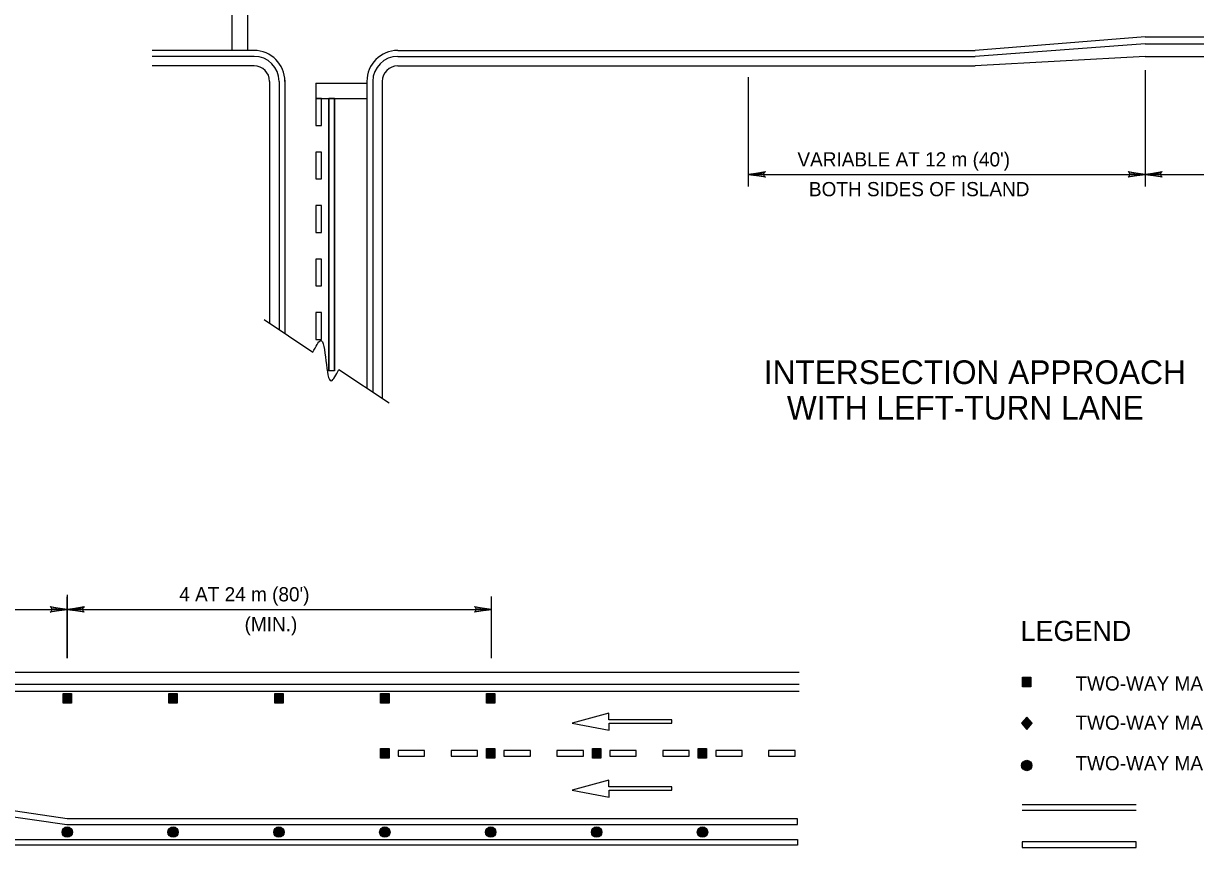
# Model space of a CAD drawing. Extents: x 639362 to 641108, y 298458 to 299646.
# Drawn here: x 639788.7 to 640036.4, y 298754.6 to 298928.7 of the extents above; entities that cross this region are included whole.
import ezdxf

# ---------------------------------------------------------------- set-up
doc = ezdxf.new("R2010")
doc.units = 0
doc.layers.add('2', color=7, linetype='Continuous')
doc.layers.add('3', color=7, linetype='Continuous')

# ---------------------------------------------------------------- blocks, each defined once
blk = doc.blocks.new('RARROW')
at = {"layer": '3'}
blk.add_lwpolyline([(-2.2695, 0.285), (-2.184875, 0.12075), (0, 0), (-2.2695, 0.285), (-2.38575, 0.384625), (0, 0), (-2.183125, -0.108), (-2.262875, -0.2705), (0, 0), (-2.38575, -0.379125), (-2.262875, -0.2705)], dxfattribs=at)

msp = doc.modelspace()

# ---------------------------------------------------------------- linework, layer by layer
at = {"layer": '2'}
for p, q in [((639832.85, 298922.95), (639832.85, 298950.59)), ((639836.15, 298922.95), (639836.15, 298950.59)), ((640025.73, 298925.85), (639989.83, 298922.95)), ((640025.73, 298925.85), (640169.33, 298925.85)), ((639837.77, 298922.95), (639815.93, 298922.95)), ((639867.83, 298922.95), (639989.83, 298922.95)), ((640025.73, 298924.35), (639989.83, 298921.72)), ((640025.73, 298924.35), (640169.33, 298924.35)), ((639837.47, 298921.72), (639815.93, 298921.72)), ((639837.47, 298919.72), (639815.93, 298919.72)), ((639867.83, 298921.72), (639989.83, 298921.72)), ((639867.83, 298919.72), (639989.83, 298919.72)), ((640025.73, 298921.72), (639989.83, 298919.72)), ((640025.73, 298921.72), (640169.33, 298921.72)), ((639941.89, 298917.32), (639941.89, 298894.23)), ((640025.73, 298918.79), (640025.73, 298894.23)), ((639840.75, 298916.44), (639840.75, 298865.35)), ((639842.75, 298916.44), (639842.75, 298864.01)), ((639843.98, 298916.69), (639843.98, 298863.19)), ((639850.53, 298916.09), (639850.53, 298912.79)), ((639850.53, 298916.09), (639861.32, 298916.09)), ((639861.32, 298916.53), (639861.32, 298851.64)), ((639862.55, 298916.44), (639862.55, 298850.81)), ((639864.55, 298916.44), (639864.55, 298849.48)), ((639850.53, 298912.79), (639861.32, 298912.79)), ((639854.47, 298912.79), (639853.27, 298912.79)), ((639853.27, 298912.79), (639853.27, 298855.27)), ((639853.27, 298855.27), (639853.27, 298912.79)), ((639853.27, 298912.79), (639854.47, 298912.79)), ((639854.47, 298855.27), (639854.47, 298912.79)), ((639854.47, 298912.79), (639854.47, 298855.27)), ((639941.89, 298896.78), (640025.73, 298896.78)), ((640025.73, 298896.78), (640169.33, 298896.78)), ((639839.62, 298866.1), (639849.91, 298859.24)), ((639854.47, 298855.27), (639853.27, 298855.27)), ((639855.4, 298855.58), (639866.03, 298848.49)), ((639797.99, 298807.92), (639797.99, 298794.58)), ((639798, 298794.58), (639798, 298807.5)), ((639887.61, 298794.58), (639887.61, 298807.59)), ((639585.52, 298804.88), (639797.99, 298804.88)), ((639798.01, 298804.88), (639887.61, 298804.88)), ((639431.25, 298791.58), (639952.64, 298791.58)), ((639789.19, 298791.58), (639951.12, 298791.58)), ((639431.25, 298789.08), (639952.64, 298789.08)), ((639789.84, 298789.08), (639951.12, 298789.08)), ((639999.84, 298790.57), (640001.61, 298790.57)), ((639999.84, 298788.53), (639999.84, 298790.57)), ((640001.61, 298788.53), (639999.84, 298788.53)), ((640000.01, 298790.4), (640001.43, 298790.4)), ((640000.01, 298788.71), (640000.01, 298790.4)), ((640001.43, 298788.71), (640000.01, 298788.71)), ((640000.19, 298790.22), (640001.26, 298790.22)), ((640000.19, 298788.89), (640000.19, 298790.22)), ((640001.26, 298788.89), (640000.19, 298788.89)), ((640000.37, 298789.07), (640000.37, 298790.04)), ((640000.37, 298790.04), (640001.08, 298790.04)), ((640001.08, 298789.07), (640000.37, 298789.07)), ((640000.55, 298789.87), (640000.9, 298789.87)), ((640000.55, 298789.24), (640000.55, 298789.87)), ((640000.9, 298789.24), (640000.55, 298789.24)), ((640000.72, 298789.69), (640000.72, 298789.42)), ((640000.9, 298789.87), (640000.9, 298789.24)), ((640001.08, 298790.04), (640001.08, 298789.07)), ((640001.26, 298790.22), (640001.26, 298788.89)), ((640001.43, 298790.4), (640001.43, 298788.71)), ((640001.61, 298790.57), (640001.61, 298788.53)), ((639431.25, 298787.58), (639952.64, 298787.58)), ((639790.24, 298787.58), (639951.12, 298787.58)), ((639797.11, 298785.06), (639797.11, 298787.1)), ((639797.11, 298787.1), (639798.88, 298787.1)), ((639797.28, 298785.23), (639797.28, 298786.92)), ((639797.28, 298786.92), (639798.7, 298786.92)), ((639797.46, 298785.41), (639797.46, 298786.74)), ((639797.46, 298786.74), (639798.53, 298786.74)), ((639797.64, 298785.59), (639797.64, 298786.56)), ((639797.64, 298786.56), (639798.35, 298786.56)), ((639797.82, 298785.76), (639797.82, 298786.39)), ((639797.82, 298786.39), (639798.17, 298786.39)), ((639798.17, 298785.76), (639797.82, 298785.76)), ((639798, 298785.94), (639798, 298786.21)), ((639798.17, 298786.39), (639798.17, 298785.76)), ((639798.35, 298786.56), (639798.35, 298785.59)), ((639798.53, 298786.74), (639798.53, 298785.41)), ((639798.7, 298786.92), (639798.7, 298785.23)), ((639798.88, 298787.1), (639798.88, 298785.06)), ((639819.47, 298785.06), (639819.47, 298787.1)), ((639819.47, 298787.1), (639821.25, 298787.1)), ((639819.65, 298785.23), (639819.65, 298786.92)), ((639819.65, 298786.92), (639821.07, 298786.92)), ((639819.83, 298785.41), (639819.83, 298786.74)), ((639819.83, 298786.74), (639820.89, 298786.74)), ((639820.01, 298785.59), (639820.01, 298786.56)), ((639820.01, 298786.56), (639820.72, 298786.56)), ((639820.18, 298785.76), (639820.18, 298786.39)), ((639820.18, 298786.39), (639820.54, 298786.39)), ((639820.54, 298785.76), (639820.18, 298785.76)), ((639820.36, 298785.94), (639820.36, 298786.21)), ((639820.54, 298786.39), (639820.54, 298785.76)), ((639820.72, 298786.56), (639820.72, 298785.59)), ((639820.89, 298786.74), (639820.89, 298785.41)), ((639821.07, 298786.92), (639821.07, 298785.23)), ((639821.25, 298787.1), (639821.25, 298785.06)), ((639841.84, 298785.06), (639841.84, 298787.1)), ((639841.84, 298787.1), (639843.62, 298787.1)), ((639842.02, 298785.23), (639842.02, 298786.92)), ((639842.02, 298786.92), (639843.44, 298786.92)), ((639842.2, 298785.41), (639842.2, 298786.74)), ((639842.2, 298786.74), (639843.26, 298786.74)), ((639842.37, 298785.59), (639842.37, 298786.56)), ((639842.37, 298786.56), (639843.08, 298786.56)), ((639842.55, 298785.76), (639842.55, 298786.39)), ((639842.55, 298786.39), (639842.91, 298786.39)), ((639842.91, 298785.76), (639842.55, 298785.76)), ((639842.73, 298785.94), (639842.73, 298786.21)), ((639842.91, 298786.39), (639842.91, 298785.76)), ((639843.08, 298786.56), (639843.08, 298785.59)), ((639843.26, 298786.74), (639843.26, 298785.41)), ((639843.44, 298786.92), (639843.44, 298785.23)), ((639843.62, 298787.1), (639843.62, 298785.06)), ((639864.21, 298785.06), (639864.21, 298787.1)), ((639864.21, 298787.1), (639865.98, 298787.1)), ((639864.39, 298785.23), (639864.39, 298786.92)), ((639864.39, 298786.92), (639865.81, 298786.92)), ((639864.56, 298785.41), (639864.56, 298786.74)), ((639864.56, 298786.74), (639865.63, 298786.74)), ((639864.74, 298785.59), (639864.74, 298786.56)), ((639864.74, 298786.56), (639865.45, 298786.56)), ((639864.92, 298785.76), (639864.92, 298786.39)), ((639864.92, 298786.39), (639865.27, 298786.39)), ((639865.27, 298785.76), (639864.92, 298785.76)), ((639865.1, 298785.94), (639865.1, 298786.21)), ((639865.27, 298786.39), (639865.27, 298785.76)), ((639865.45, 298786.56), (639865.45, 298785.59)), ((639865.63, 298786.74), (639865.63, 298785.41)), ((639865.81, 298786.92), (639865.81, 298785.23)), ((639865.98, 298787.1), (639865.98, 298785.06)), ((639886.58, 298785.06), (639886.58, 298787.1)), ((639886.58, 298787.1), (639888.35, 298787.1)), ((639886.75, 298785.23), (639886.75, 298786.92)), ((639886.75, 298786.92), (639888.17, 298786.92)), ((639886.93, 298785.41), (639886.93, 298786.74)), ((639886.93, 298786.74), (639888, 298786.74)), ((639887.11, 298785.59), (639887.11, 298786.56)), ((639887.11, 298786.56), (639887.82, 298786.56)), ((639887.29, 298785.76), (639887.29, 298786.39)), ((639887.29, 298786.39), (639887.64, 298786.39)), ((639887.64, 298785.76), (639887.29, 298785.76)), ((639887.47, 298785.94), (639887.47, 298786.21)), ((639887.64, 298786.39), (639887.64, 298785.76)), ((639887.82, 298786.56), (639887.82, 298785.59)), ((639888, 298786.74), (639888, 298785.41)), ((639888.17, 298786.92), (639888.17, 298785.23)), ((639888.35, 298787.1), (639888.35, 298785.06)), ((639798.88, 298785.06), (639797.11, 298785.06)), ((639798.7, 298785.23), (639797.28, 298785.23)), ((639798.53, 298785.41), (639797.46, 298785.41)), ((639798.35, 298785.59), (639797.64, 298785.59)), ((639821.25, 298785.06), (639819.47, 298785.06)), ((639821.07, 298785.23), (639819.65, 298785.23)), ((639820.89, 298785.41), (639819.83, 298785.41)), ((639820.72, 298785.59), (639820.01, 298785.59)), ((639843.62, 298785.06), (639841.84, 298785.06)), ((639843.44, 298785.23), (639842.02, 298785.23)), ((639843.26, 298785.41), (639842.2, 298785.41)), ((639843.08, 298785.59), (639842.37, 298785.59)), ((639865.98, 298785.06), (639864.21, 298785.06)), ((639865.81, 298785.23), (639864.39, 298785.23)), ((639865.63, 298785.41), (639864.56, 298785.41)), ((639865.45, 298785.59), (639864.74, 298785.59)), ((639888.35, 298785.06), (639886.58, 298785.06)), ((639888.17, 298785.23), (639886.75, 298785.23)), ((639888, 298785.41), (639886.93, 298785.41)), ((639887.82, 298785.59), (639887.11, 298785.59)), ((639912.39, 298782.98), (639904.67, 298780.86)), ((639904.67, 298780.86), (639912.47, 298779.39)), ((639912.39, 298781.54), (639912.39, 298782.98)), ((639925.72, 298781.54), (639912.39, 298781.54)), ((639912.47, 298779.39), (639912.47, 298780.83)), ((639912.47, 298780.83), (639925.72, 298780.83)), ((639925.72, 298780.83), (639925.72, 298781.54)), ((640000.75, 298782.1), (639999.62, 298780.8)), ((639999.62, 298780.8), (640000.75, 298779.51)), ((639999.62, 298780.8), (640001.88, 298780.8)), ((639999.73, 298780.92), (640000.85, 298779.63)), ((640000.85, 298781.98), (639999.74, 298780.7)), ((640000.96, 298781.86), (639999.83, 298780.56)), ((639999.83, 298781.04), (640000.96, 298779.75)), ((640001.06, 298781.74), (639999.93, 298780.44)), ((639999.93, 298781.16), (640001.06, 298779.87)), ((640001.17, 298781.62), (640000.04, 298780.32)), ((640000.04, 298781.28), (640001.17, 298779.99)), ((640001.27, 298781.5), (640000.14, 298780.2)), ((640000.14, 298781.4), (640001.27, 298780.11)), ((640000.25, 298781.52), (640001.38, 298780.23)), ((640001.38, 298781.38), (640000.25, 298780.08)), ((640000.35, 298781.64), (640001.48, 298780.35)), ((640001.48, 298781.26), (640000.35, 298779.96)), ((640000.46, 298781.76), (640001.58, 298780.47)), ((640001.58, 298781.14), (640000.46, 298779.84)), ((640000.56, 298781.88), (640001.69, 298780.59)), ((640001.69, 298781.02), (640000.56, 298779.72)), ((640000.67, 298782), (640001.79, 298780.71)), ((640001.79, 298780.9), (640000.67, 298779.6)), ((640001.88, 298780.8), (640000.75, 298782.1)), ((640000.75, 298782.1), (640000.75, 298779.51)), ((640000.75, 298779.51), (640001.88, 298780.8)), ((639864.21, 298773.41), (639864.21, 298775.45)), ((639864.21, 298775.45), (639865.98, 298775.45)), ((639865.98, 298773.41), (639864.21, 298773.41)), ((639864.39, 298773.59), (639864.39, 298775.27)), ((639864.39, 298775.27), (639865.81, 298775.27)), ((639865.81, 298773.59), (639864.39, 298773.59)), ((639864.56, 298773.77), (639864.56, 298775.09)), ((639864.56, 298775.09), (639865.63, 298775.09)), ((639865.63, 298773.77), (639864.56, 298773.77)), ((639864.74, 298773.94), (639864.74, 298774.92)), ((639864.74, 298774.92), (639865.45, 298774.92)), ((639865.45, 298773.94), (639864.74, 298773.94)), ((639864.92, 298774.12), (639864.92, 298774.74)), ((639864.92, 298774.74), (639865.27, 298774.74)), ((639865.27, 298774.12), (639864.92, 298774.12)), ((639865.1, 298774.29), (639865.1, 298774.56)), ((639865.27, 298774.74), (639865.27, 298774.12)), ((639865.45, 298774.92), (639865.45, 298773.94)), ((639865.63, 298775.09), (639865.63, 298773.77)), ((639865.81, 298775.27), (639865.81, 298773.59)), ((639865.98, 298775.45), (639865.98, 298773.41)), ((639873.49, 298775.03), (639867.89, 298775.03)), ((639867.89, 298775.03), (639867.89, 298773.83)), ((639867.89, 298773.83), (639873.49, 298773.83)), ((639873.49, 298773.83), (639873.49, 298775.03)), ((639884.67, 298775.03), (639879.08, 298775.03)), ((639879.08, 298775.03), (639879.08, 298773.83)), ((639879.08, 298773.83), (639884.67, 298773.83)), ((639884.67, 298773.83), (639884.67, 298775.03)), ((639886.58, 298773.41), (639886.58, 298775.45)), ((639886.58, 298775.45), (639888.35, 298775.45)), ((639888.35, 298773.41), (639886.58, 298773.41)), ((639886.75, 298773.59), (639886.75, 298775.27)), ((639886.75, 298775.27), (639888.17, 298775.27)), ((639888.17, 298773.59), (639886.75, 298773.59)), ((639886.93, 298773.77), (639886.93, 298775.09)), ((639886.93, 298775.09), (639888, 298775.09)), ((639888, 298773.77), (639886.93, 298773.77)), ((639887.11, 298773.94), (639887.11, 298774.92)), ((639887.11, 298774.92), (639887.82, 298774.92)), ((639887.82, 298773.94), (639887.11, 298773.94)), ((639887.29, 298774.12), (639887.29, 298774.74)), ((639887.29, 298774.74), (639887.64, 298774.74)), ((639887.64, 298774.12), (639887.29, 298774.12)), ((639887.47, 298774.29), (639887.47, 298774.56)), ((639887.64, 298774.74), (639887.64, 298774.12)), ((639887.82, 298774.92), (639887.82, 298773.94)), ((639888, 298775.09), (639888, 298773.77)), ((639888.17, 298775.27), (639888.17, 298773.59)), ((639888.35, 298775.45), (639888.35, 298773.41)), ((639895.85, 298775.03), (639890.26, 298775.03)), ((639890.26, 298775.03), (639890.26, 298773.83)), ((639890.26, 298773.83), (639895.85, 298773.83)), ((639895.85, 298773.83), (639895.85, 298775.03)), ((639907.04, 298775.03), (639901.45, 298775.03)), ((639901.45, 298775.03), (639901.45, 298773.83)), ((639901.45, 298773.83), (639907.04, 298773.83)), ((639907.04, 298773.83), (639907.04, 298775.03)), ((639908.94, 298773.41), (639908.94, 298775.45)), ((639908.94, 298775.45), (639910.72, 298775.45)), ((639910.72, 298773.41), (639908.94, 298773.41)), ((639909.12, 298773.59), (639909.12, 298775.27)), ((639909.12, 298775.27), (639910.54, 298775.27)), ((639910.54, 298773.59), (639909.12, 298773.59)), ((639909.3, 298773.77), (639909.3, 298775.09)), ((639909.3, 298775.09), (639910.36, 298775.09)), ((639910.36, 298773.77), (639909.3, 298773.77)), ((639909.48, 298773.94), (639909.48, 298774.92)), ((639909.48, 298774.92), (639910.19, 298774.92)), ((639910.19, 298773.94), (639909.48, 298773.94)), ((639909.65, 298774.12), (639909.65, 298774.74)), ((639909.65, 298774.74), (639910.01, 298774.74)), ((639910.01, 298774.12), (639909.65, 298774.12)), ((639909.83, 298774.29), (639909.83, 298774.56)), ((639910.01, 298774.74), (639910.01, 298774.12)), ((639910.19, 298774.92), (639910.19, 298773.94)), ((639910.36, 298775.09), (639910.36, 298773.77)), ((639910.54, 298775.27), (639910.54, 298773.59)), ((639910.72, 298775.45), (639910.72, 298773.41)), ((639918.22, 298775.03), (639912.63, 298775.03)), ((639912.63, 298775.03), (639912.63, 298773.83)), ((639912.63, 298773.83), (639918.22, 298773.83)), ((639918.22, 298773.83), (639918.22, 298775.03)), ((639929.41, 298775.03), (639923.81, 298775.03)), ((639923.81, 298775.03), (639923.81, 298773.83)), ((639923.81, 298773.83), (639929.41, 298773.83)), ((639929.41, 298773.83), (639929.41, 298775.03)), ((639931.31, 298773.41), (639931.31, 298775.45)), ((639931.31, 298775.45), (639933.09, 298775.45)), ((639933.09, 298773.41), (639931.31, 298773.41)), ((639931.49, 298773.59), (639931.49, 298775.27)), ((639931.49, 298775.27), (639932.91, 298775.27)), ((639932.91, 298773.59), (639931.49, 298773.59)), ((639931.67, 298773.77), (639931.67, 298775.09)), ((639931.67, 298775.09), (639932.73, 298775.09)), ((639932.73, 298773.77), (639931.67, 298773.77)), ((639931.84, 298773.94), (639931.84, 298774.92)), ((639931.84, 298774.92), (639932.55, 298774.92)), ((639932.55, 298773.94), (639931.84, 298773.94)), ((639932.02, 298774.12), (639932.02, 298774.74)), ((639932.02, 298774.74), (639932.38, 298774.74)), ((639932.38, 298774.12), (639932.02, 298774.12)), ((639932.2, 298774.29), (639932.2, 298774.56)), ((639932.38, 298774.74), (639932.38, 298774.12)), ((639932.55, 298774.92), (639932.55, 298773.94)), ((639932.73, 298775.09), (639932.73, 298773.77)), ((639932.91, 298775.27), (639932.91, 298773.59)), ((639933.09, 298775.45), (639933.09, 298773.41)), ((639940.59, 298775.03), (639935, 298775.03)), ((639935, 298775.03), (639935, 298773.83)), ((639935, 298773.83), (639940.59, 298773.83)), ((639940.59, 298773.83), (639940.59, 298775.03)), ((639951.77, 298775.03), (639946.18, 298775.03)), ((639946.18, 298775.03), (639946.18, 298773.83)), ((639946.18, 298773.83), (639951.77, 298773.83)), ((639951.77, 298773.83), (639951.77, 298775.03)), ((639719.64, 298770.96), (639797.91, 298759.39)), ((639798, 298760.59), (639719.73, 298772.16)), ((639912.39, 298768.82), (639904.67, 298766.7)), ((639912.39, 298767.38), (639912.39, 298768.82)), ((639904.67, 298766.7), (639912.47, 298765.23)), ((639925.72, 298767.38), (639912.39, 298767.38)), ((639912.47, 298765.23), (639912.47, 298766.67)), ((639912.47, 298766.67), (639925.72, 298766.67)), ((639925.72, 298766.67), (639925.72, 298767.38)), ((640023.81, 298763.56), (639999.76, 298763.56)), ((640023.81, 298762.36), (639999.76, 298762.36)), ((639797.91, 298759.39), (639952.26, 298759.39)), ((639952.26, 298760.59), (639798, 298760.59)), ((639952.26, 298759.39), (639952.26, 298760.59)), ((639663.88, 298756.28), (639952.26, 298756.28)), ((639952.26, 298756.28), (639952.26, 298755.08)), ((639952.26, 298755.08), (639663.79, 298755.08)), ((640023.81, 298755.75), (639999.76, 298755.75)), ((639999.76, 298755.75), (639999.76, 298754.55)), ((639999.76, 298754.55), (640023.81, 298754.55)), ((640023.81, 298754.55), (640023.81, 298755.75))]:
    msp.add_line(p, q, dxfattribs=at)
for points in [[(639850.53, 298907.13), (639851.73, 298907.13), (639851.73, 298912.79), (639850.53, 298912.79)], [(639850.53, 298895.83), (639851.73, 298895.83), (639851.73, 298901.48), (639850.53, 298901.48)], [(639850.53, 298884.52), (639851.73, 298884.52), (639851.73, 298890.18), (639850.53, 298890.18)], [(639850.53, 298873.22), (639851.73, 298873.22), (639851.73, 298878.87), (639850.53, 298878.87)], [(639850.53, 298861.91), (639851.73, 298861.91), (639851.73, 298867.57), (639850.53, 298867.57)]]:
    msp.add_lwpolyline(points, close=True, dxfattribs=at)
for centre, radius in [((640000.72, 298771.89), 1.1), ((640000.72, 298771.89), 1.02), ((640000.72, 298771.89), 0.946), ((640000.72, 298771.89), 0.868), ((640000.72, 298771.89), 0.789), ((640000.72, 298771.89), 0.711), ((640000.72, 298771.89), 0.633), ((640000.72, 298771.89), 0.554), ((640000.72, 298771.89), 0.476), ((640000.72, 298771.89), 0.398), ((640000.72, 298771.89), 0.32), ((640000.72, 298771.89), 0.241), ((640000.72, 298771.89), 0.163), ((640000.72, 298771.89), 0.0846), ((639798.01, 298757.83), 1.1), ((639798.01, 298757.83), 1.02), ((639798.01, 298757.83), 0.946), ((639798.01, 298757.83), 0.868), ((639798.01, 298757.83), 0.789), ((639798.01, 298757.83), 0.711), ((639798.01, 298757.83), 0.633), ((639820.36, 298757.83), 1.1), ((639820.36, 298757.83), 1.02), ((639820.36, 298757.83), 0.946), ((639820.36, 298757.83), 0.868), ((639820.36, 298757.83), 0.789), ((639820.36, 298757.83), 0.711), ((639820.36, 298757.83), 0.633), ((639842.73, 298757.83), 1.1), ((639842.73, 298757.83), 1.02), ((639842.73, 298757.83), 0.946), ((639842.73, 298757.83), 0.868), ((639842.73, 298757.83), 0.789), ((639842.73, 298757.83), 0.711), ((639842.73, 298757.83), 0.633), ((639865.1, 298757.83), 1.1), ((639865.1, 298757.83), 1.02), ((639865.1, 298757.83), 0.946), ((639865.1, 298757.83), 0.868), ((639865.1, 298757.83), 0.789), ((639865.1, 298757.83), 0.711), ((639865.1, 298757.83), 0.633), ((639887.47, 298757.83), 1.1), ((639887.47, 298757.83), 1.02), ((639887.47, 298757.83), 0.946), ((639887.47, 298757.83), 0.868), ((639887.47, 298757.83), 0.789), ((639887.47, 298757.83), 0.711), ((639887.47, 298757.83), 0.633), ((639909.85, 298757.83), 1.1), ((639909.85, 298757.83), 1.02), ((639909.85, 298757.83), 0.946), ((639909.85, 298757.83), 0.868), ((639909.85, 298757.83), 0.789), ((639909.85, 298757.83), 0.711), ((639909.85, 298757.83), 0.633), ((639932.22, 298757.83), 1.1), ((639932.22, 298757.83), 1.02), ((639932.22, 298757.83), 0.946), ((639932.22, 298757.83), 0.868), ((639932.22, 298757.83), 0.789), ((639932.22, 298757.83), 0.711), ((639932.22, 298757.83), 0.633), ((639798.01, 298757.83), 0.554), ((639798.01, 298757.83), 0.476), ((639798.01, 298757.83), 0.398), ((639798.01, 298757.83), 0.32), ((639798.01, 298757.83), 0.241), ((639798.01, 298757.83), 0.163), ((639798.01, 298757.83), 0.0846), ((639820.36, 298757.83), 0.554), ((639820.36, 298757.83), 0.476), ((639820.36, 298757.83), 0.398), ((639820.36, 298757.83), 0.32), ((639820.36, 298757.83), 0.241), ((639820.36, 298757.83), 0.163), ((639820.36, 298757.83), 0.0846), ((639842.73, 298757.83), 0.554), ((639842.73, 298757.83), 0.476), ((639842.73, 298757.83), 0.398), ((639842.73, 298757.83), 0.32), ((639842.73, 298757.83), 0.241), ((639842.73, 298757.83), 0.163), ((639842.73, 298757.83), 0.0846), ((639865.1, 298757.83), 0.554), ((639865.1, 298757.83), 0.476), ((639865.1, 298757.83), 0.398), ((639865.1, 298757.83), 0.32), ((639865.1, 298757.83), 0.241), ((639865.1, 298757.83), 0.163), ((639865.1, 298757.83), 0.0846), ((639887.47, 298757.83), 0.554), ((639887.47, 298757.83), 0.476), ((639887.47, 298757.83), 0.398), ((639887.47, 298757.83), 0.32), ((639887.47, 298757.83), 0.241), ((639887.47, 298757.83), 0.163), ((639887.47, 298757.83), 0.0846), ((639909.85, 298757.83), 0.554), ((639909.85, 298757.83), 0.476), ((639909.85, 298757.83), 0.398), ((639909.85, 298757.83), 0.32), ((639909.85, 298757.83), 0.241), ((639909.85, 298757.83), 0.163), ((639909.85, 298757.83), 0.0846), ((639932.22, 298757.83), 0.554), ((639932.22, 298757.83), 0.476), ((639932.22, 298757.83), 0.398), ((639932.22, 298757.83), 0.32), ((639932.22, 298757.83), 0.241), ((639932.22, 298757.83), 0.163), ((639932.22, 298757.83), 0.0846)]:
    msp.add_circle(centre, radius, dxfattribs=at)
for centre, radius, start, end in [((639837.47, 298916.44), 6.52, 0, 90), ((639867.83, 298916.44), 6.52, 90, 180), ((639837.47, 298916.44), 5.28, 0, 90), ((639837.47, 298916.44), 3.28, 0, 90), ((639867.83, 298916.44), 5.28, 90, 180), ((639867.83, 298916.44), 3.28, 90, 180)]:
    msp.add_arc(centre, radius, start, end, dxfattribs=at)
msp.add_spline([(639849.91, 298859.24), (639851.51, 298861.66), (639853.8, 298853.18), (639855.4, 298855.58)], degree=3, dxfattribs=at)

# ---------------------------------------------------------------- block references
at = {"layer": '2', "xscale": 1.5089217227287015, "yscale": 1.5711553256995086, "rotation": 180}
for p in [(639941.89, 298896.78), (640025.73, 298896.78), (639798.01, 298804.88)]:
    msp.add_blockref('RARROW', p, dxfattribs=at)
at = {"layer": '2', "xscale": 1.5089217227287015, "yscale": 1.5711553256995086}
for p in [(640025.73, 298896.78), (639797.99, 298804.88), (639887.61, 298804.88)]:
    msp.add_blockref('RARROW', p, dxfattribs=at)

# ---------------------------------------------------------------- texts
at = {"layer": '2'}
for s, height, p in [("VARIABLE AT 12 m (40')", 3, (639952.27, 298898.46)), ('BOTH SIDES OF ISLAND', 3, (639954.7, 298892.17)), ('INTERSECTION APPROACH', 5, (639945.16, 298852.49)), ('WITH LEFT-TURN LANE', 5, (639950.04, 298844.99)), ("4 AT 24 m (80')", 3, (639821.66, 298806.57)), ('(MIN.)', 3, (639835.47, 298800.27)), ('LEGEND', 4.25, (639999.42, 298798.2)), ('TWO-WAY MARKER WITH WHITE/BLANK REFLECTOR', 3, (640011, 298787.73)), ('TWO-WAY MARKER WITH YELLOW/YELLOW REFLECTOR', 3, (640011, 298770.88))]:
    msp.add_text(s, height=height, dxfattribs=at).set_placement(p)
msp.add_text('TWO-WAY MARKER WITH YELLOW/BLANK REFLECTOR', height=3, rotation=360, dxfattribs=at).set_placement((640011, 298779.44))

doc.saveas('drawing.dxf')
